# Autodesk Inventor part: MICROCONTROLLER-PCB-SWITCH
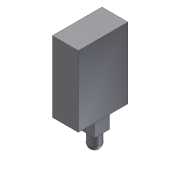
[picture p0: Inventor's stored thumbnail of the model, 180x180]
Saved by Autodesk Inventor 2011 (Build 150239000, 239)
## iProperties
Created: 2010-06
Part Number: MICROCONTROLLER-PCB-SWITCH
Document SubType Name: Modeling
Designer: kurdi
Density: 1 g/cm^3
Author: kurdi
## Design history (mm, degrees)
feature "Base1"
sketch "Sketch1"
  geometry: C1 r 1.587 at (1.9, -1.9); 1 further point
  constraints: 1 centre point
  dimensions: "d0" = 3.175 diameter of C1
extrude "Extrusion1" join sketch "Sketch1" distance "d1" = 4.318; taper "d2" = 0 deg
fillet "Fillet1" dims "d3" = 1.5875
node "NONE"
